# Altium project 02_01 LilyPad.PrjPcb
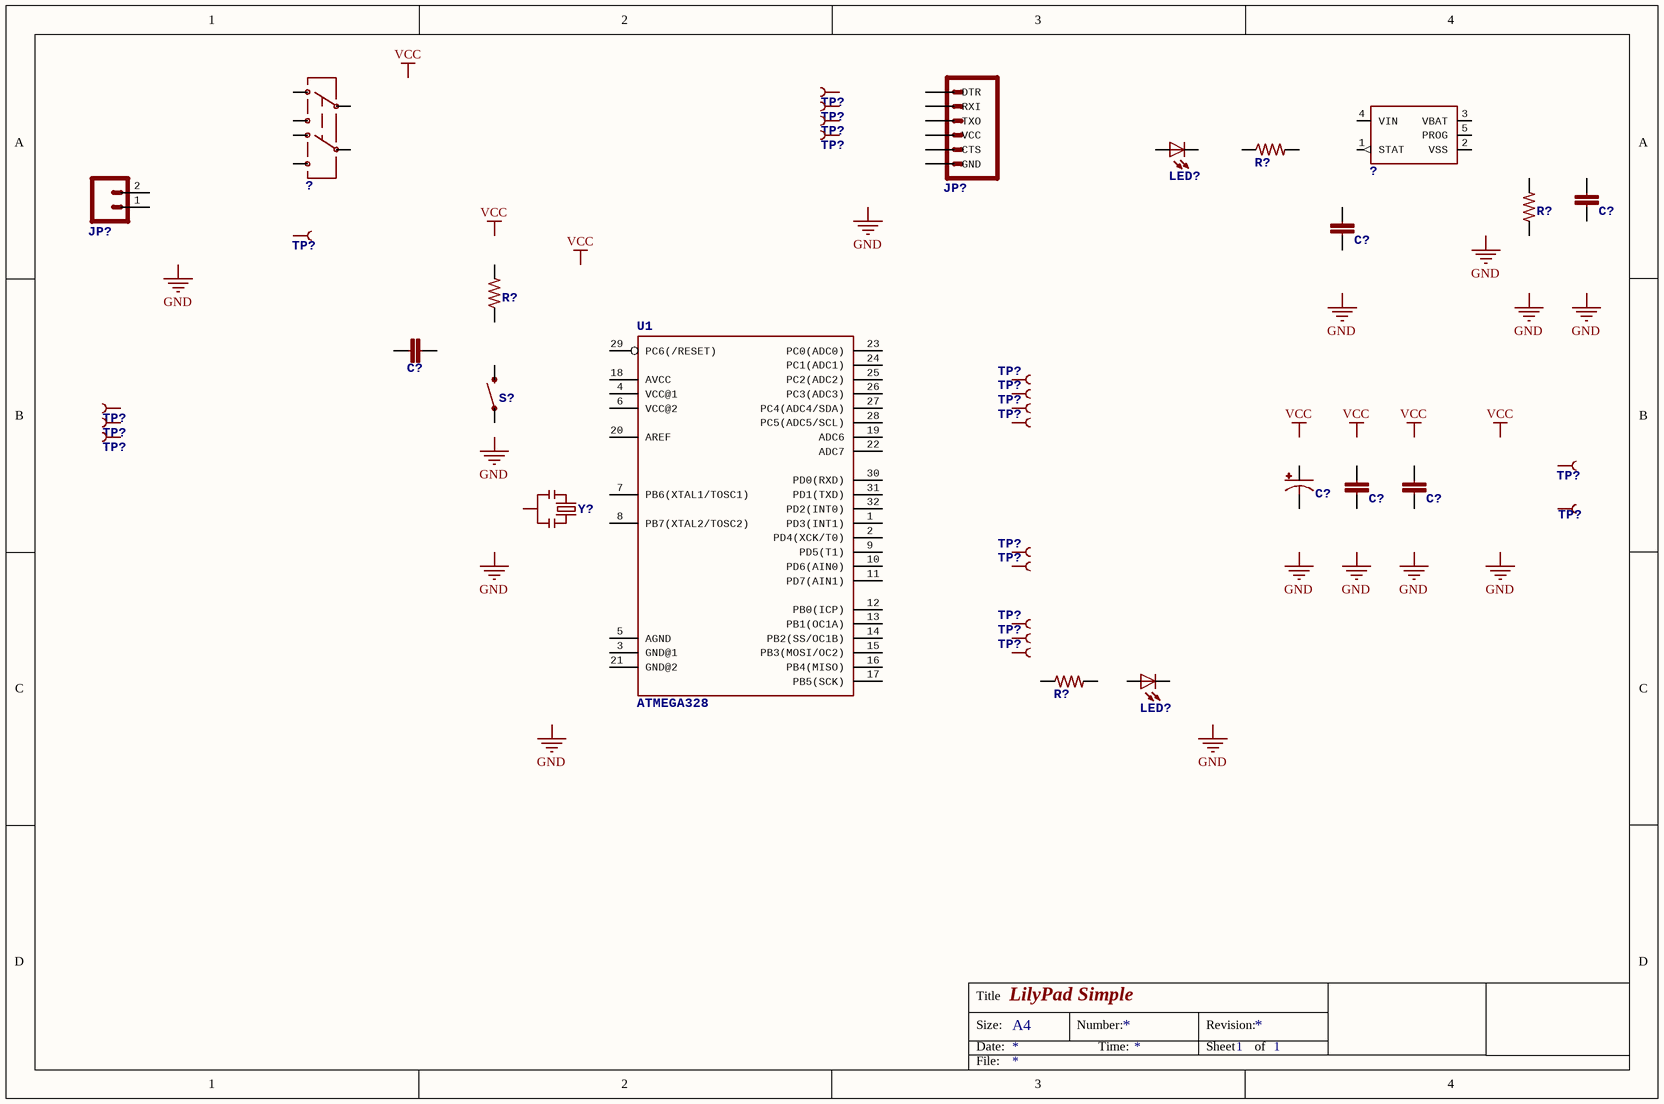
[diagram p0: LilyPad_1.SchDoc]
1 sheet, 38 parts. Net scope: global (net labels, ports and power ports of the same name join across sheets).

## Sheet LilyPad_1.SchDoc: LilyPad Simple
size A4; SheetNumber: 1; SheetTotal: 1

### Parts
(Parts that share a designator on the sheet are numbered #1, #2 ... from top to bottom, then left to right.)
?#1  AYZ0202  [AYZ0202]  (value not drawn)
?#2  MCP73831  [SOT23-5]  (value not drawn)
C?#1  CAP0402-CAP  [0402-CAP]  (value not drawn)
C?#2  CAP0402-CAP  [0402-CAP]  (value not drawn)
C?#3  CAP0402-CAP  [0402-CAP]  (value not drawn)
C?#4  CAP_POL3528  [EIA3528]  (value not drawn)
C?#5  CAP0402-CAP  [0402-CAP]  (value not drawn)
C?#6  CAP0402-CAP  [0402-CAP]  (value not drawn)
JP?#1  ARDUINO_SERIAL_PROGRAMSMD  [1X06-SMD]  (value not drawn)
JP?#2  M02-JST-2MM-SMT  [JST-2-SMD]  (value not drawn)
LED?#1  LED0603  [LED-0603]  (value not drawn)
LED?#2  LED0603  [LED-0603]  (value not drawn)
R?#1  RESISTOR0402-RES  [0402-RES]  (value not drawn)
R?#2  RESISTOR0402-RES  [0402-RES]  (value not drawn)
R?#3  RESISTOR0402-RES  [0402-RES]  (value not drawn)
R?#4  RESISTOR0402-RES  [0402-RES]  (value not drawn)
S?  SWITCH-MOMENTARY-2SMD-2  [TACTILE_SWITCH_SMD-2]  (value not drawn)
TP?#1  TEST-POINT3X5  [PAD.03X.05]  (value not drawn)
TP?#2  TEST-POINT3X5  [PAD.03X.05]  (value not drawn)
TP?#3  TEST-POINT3X5  [PAD.03X.05]  (value not drawn)
TP?#4  TEST-POINT3X5  [PAD.03X.05]  (value not drawn)
TP?#5  TEST-POINT3X5  [PAD.03X.05]  (value not drawn)
TP?#6  CONN  [PETAL-LONG-2]  (value not drawn)
TP?#7  CONN  [PETAL-LONG-2]  (value not drawn)
TP?#8  TEST-POINT3X5  [PAD.03X.05]  (value not drawn)
TP?#9  CONN  [PETAL-LONG-2]  (value not drawn)
TP?#10  TEST-POINT3X5  [PAD.03X.05]  (value not drawn)
TP?#11  CONN  [PETAL-LONG-2]  (value not drawn)
TP?#12  TEST-POINT3X5  [PAD.03X.05]  (value not drawn)
TP?#13  CONN  [PETAL-LONG-2]  (value not drawn)
TP?#14  CONN  [PETAL-LONG-2]  (value not drawn)
TP?#15  CONN  [PETAL-LONG-2]  (value not drawn)
TP?#16  CONN  [PETAL-LONG-2]  (value not drawn)
TP?#17  CONN  [PETAL-LONG-2]  (value not drawn)
TP?#18  CONN  [PETAL-LONG-2]  (value not drawn)
TP?#19  CONN  [PETAL-LONG-2]  (value not drawn)
U1  ATMEGA328  [TQFP32-08]
Y?  RESONATORSMD  [RESONATOR-SMD]  (value not drawn)

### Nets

Not connected (* = marked no-connect by the designer): ?#1 1(3) 2 3(1) 4(6) 5 6(4); ?#2 1(STAT) 2(VSS) 3(VBAT) 4(VIN) 5(PROG); C?#1 1 2; C?#2 1 2; C?#3 1 2; C?#4 A(+) C(-); C?#5 1 2; C?#6 1 2; JP?#1 1(DTR) 2(RXI) 3(TXO) 4(VCC) 5(CTS) 6(GND); JP?#2 1 2; LED?#1 A C; LED?#2 A C; R?#1 1 2; R?#2 1 2; R?#3 1 2; R?#4 1 2; S? 1(2) 2(1); TP?#1 P$1(1); TP?#2 P$1(1); TP?#3 P$1(1); TP?#4 P$1(1); TP?#5 P$1(1); TP?#6 1; TP?#7 1; TP?#8 P$1(1); TP?#9 1; TP?#10 P$1(1); TP?#11 1; TP?#12 P$1(1); TP?#13 1; TP?#14 1; TP?#15 1; TP?#16 1; TP?#17 1; TP?#18 1; TP?#19 1; U1 1(PD3(INT1)) 2(PD4(XCK/T0)) 3(GND@1) 4(VCC@1) 5(AGND) 6(VCC@2) 7(PB6(XTAL1/TOSC1)) 8(PB7(XTAL2/TOSC2)) 9(PD5(T1)) 10(PD6(AIN0)) 11(PD7(AIN1)) 12(PB0(ICP)) 13(PB1(OC1A)) 14(PB2(SS/OC1B)) 15(PB3(MOSI/OC2)) 16(PB4(MISO)) 17(PB5(SCK)) 18(AVCC) 19(ADC6) 20(AREF) 21(GND@2) 22(ADC7) 23(PC0(ADC0)) 24(PC1(ADC1)) 25(PC2(ADC2)) 26(PC3(ADC3)) 27(PC4(ADC4/SDA)) 28(PC5(ADC5/SCL)) 29(PC6(/RESET)) 30(PD0(RXD)) 31(PD1(TXD)) 32(PD2(INT0)); Y? 1 2 3

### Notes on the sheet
- Labels drawn without touching a wire or pin: GND, VCC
